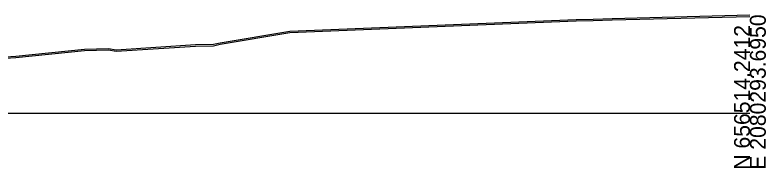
# Model space of a CAD drawing. Extents: x 1131015 to 1136271, y 133453 to 174329.
# Drawn here: x 1132510.6 to 1132643.3, y 158658 to 158685 of the extents above; entities that cross this region are included whole.
import ezdxf

# ---------------------------------------------------------------- set-up
doc = ezdxf.new("R2010")
doc.units = 0
for name, color, linetype in [('DESIGN - SHEET - Light Grid', 7, 'Continuous'), ('SURVEY - GROUND - Bottom of Topsoil Layer', 7, 'Continuous'), ('SURVEY - GROUND - Top of Ground', 7, 'Continuous')]:
    doc.layers.add(name, color=color, linetype=linetype)

msp = doc.modelspace()

# ---------------------------------------------------------------- linework, layer by layer
at = {"layer": 'DESIGN - SHEET - Light Grid'}
msp.add_line((1132340.46, 158667.66), (1132640.46, 158667.66), dxfattribs=at)
at = {"layer": 'SURVEY - GROUND - Bottom of Topsoil Layer'}
for p, q in [((1132616.14, 158684.16), (1132640.46, 158684.79)), ((1132559.15, 158681.93), (1132609.74, 158683.99)), ((1132609.74, 158683.99), (1132612.74, 158684.06)), ((1132612.74, 158684.06), (1132616.14, 158684.16)), ((1132546.82, 158679.86), (1132559.15, 158681.93)), ((1132528.49, 158678.65), (1132542.5, 158679.55)), ((1132542.5, 158679.55), (1132545.69, 158679.61)), ((1132545.69, 158679.61), (1132546.82, 158679.86)), ((1132510.73, 158677.49), (1132522.89, 158678.73)), ((1132522.89, 158678.73), (1132527.09, 158678.86)), ((1132527.09, 158678.86), (1132528.49, 158678.65)), ((1132508.93, 158677.39), (1132510.73, 158677.49))]:
    msp.add_line(p, q, dxfattribs=at)
at = {"layer": 'SURVEY - GROUND - Top of Ground'}
for p, q in [((1132612.74, 158684.31), (1132616.14, 158684.41)), ((1132616.14, 158684.41), (1132640.46, 158685.04)), ((1132559.15, 158682.18), (1132609.74, 158684.24)), ((1132609.74, 158684.24), (1132612.74, 158684.31)), ((1132546.82, 158680.11), (1132559.15, 158682.18)), ((1132522.89, 158678.98), (1132527.09, 158679.11)), ((1132527.09, 158679.11), (1132528.49, 158678.9)), ((1132528.49, 158678.9), (1132542.5, 158679.8)), ((1132542.5, 158679.8), (1132545.69, 158679.86)), ((1132545.69, 158679.86), (1132546.82, 158680.11)), ((1132508.93, 158677.64), (1132510.73, 158677.74)), ((1132510.73, 158677.74), (1132522.89, 158678.98))]:
    msp.add_line(p, q, dxfattribs=at)

# ---------------------------------------------------------------- texts
at = {"layer": 'DESIGN - SHEET - Light Grid'}
for s, p in [('E 2080293.6950', (1132643.26, 158657.66)), ('N 656514.2412', (1132640.46, 158657.66))]:
    msp.add_text(s, height=2.8, rotation=90, dxfattribs=at).set_placement(p)

doc.saveas('drawing.dxf')
